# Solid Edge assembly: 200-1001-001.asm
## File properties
Title: 200-1001-00.asm
Author: rkriggs
Template: normal.asm
Last saved by: jccrumbl
Revision: 64
Application: Solid Edge
Revision: A
Teamcenter Item Type: Item
TC Engineering Description: Valve Assembly
TC_ImportTime: 2008-07-08
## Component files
100-0003-001.par
100-0004-001.par
100-0005-001.par
500-0016-001.par
100-0006-001.par
100-0007-001.par
500-0005-001.par
100-0001-001.par
100-0002-001.par
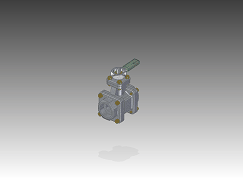
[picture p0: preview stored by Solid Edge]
